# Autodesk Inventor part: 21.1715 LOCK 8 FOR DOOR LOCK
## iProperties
Created: 2007-11
Part Number: 21.1715 LOCK 8 FOR DOOR LOCK
Material: Aluminum-6061
Document SubType Name: Modeling
Designer: Andy Moles
Mass: 2.93048 g
Surface Area: 11.258 cm^2
Volume: 1.08136 cm^3
Density: 2.71 g/cm^3
Author: Andy Moles
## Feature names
1. Base1
